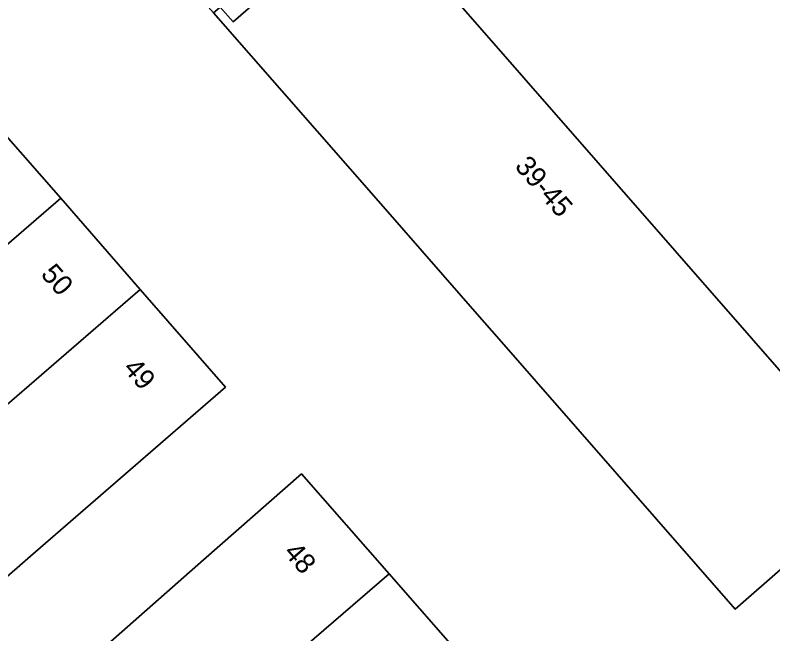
# Model space of a CAD drawing. Extents: x 160663 to 161506, y 382245 to 383291.
# Drawn here: x 160746.63 to 160784.22, y 383063.64 to 383094.33 of the extents above; entities that cross this region are included whole.
import ezdxf

# ---------------------------------------------------------------- set-up
doc = ezdxf.new("R2010")
doc.units = 0
for name, color, linetype in [('IMGEO_Erf', 7, 'Continuous'), ('IMGEO_Pand', 7, 'Continuous'), ('IMGEO_Pand_nummerreeks', 7, 'Continuous'), ('IMGEO_Pand_overbouw', 7, 'Continuous')]:
    doc.layers.add(name, color=color, linetype=linetype)

msp = doc.modelspace()

# ---------------------------------------------------------------- linework, layer by layer
at = {"layer": 'IMGEO_Erf'}
msp.add_lwpolyline([(160789.444, 383076.109), (160791.941, 383073.242), (160782.34, 383064.863), (160770.523, 383078.382), (160769.663, 383079.367), (160765.001, 383084.7), (160756.48, 383094.454), (160756.804, 383094.737), (160757.448, 383093.999), (160764.255, 383099.938), (160786.953, 383073.958)], close=True, dxfattribs=at)
for points in [[(160746.079, 383088.471), (160748.895, 383085.247), (160752.843, 383080.728), (160757.076, 383075.883), (160747.401, 383067.493), (160744.241, 383064.752)], [(160741.394, 383064.67), (160747.56, 383057.614), (160749.218, 383059.06), (160748.08, 383060.364), (160751.236, 383063.118), (160755.975, 383067.307), (160760.845, 383071.574), (160765.185, 383066.611), (160769.134, 383062.095), (160771.856, 383058.982), (160771.879, 383058.88), (160773.339, 383057.204), (160776.347, 383053.751), (160770.736, 383048.852), (160773.152, 383046.089), (160781.278, 383053.198), (160782.484, 383054.246), (160781.181, 383055.738), (160785.226, 383059.27)]]:
    msp.add_lwpolyline(points, dxfattribs=at)
at = {"layer": 'IMGEO_Pand'}
for points in [[(160764.255, 383099.938), (160757.448, 383093.999), (160756.804, 383094.737), (160756.48, 383094.454), (160765.001, 383084.7), (160769.663, 383079.367), (160770.523, 383078.382), (160782.34, 383064.863), (160791.941, 383073.242), (160789.444, 383076.109), (160786.953, 383073.958)], [(160736.016, 383074.127), (160748.895, 383085.247), (160746.079, 383088.471), (160741.125, 383084.148), (160739.68, 383085.812), (160735.027, 383081.714), (160731.764, 383078.977)], [(160736.016, 383074.127), (160739.971, 383069.614), (160752.843, 383080.728), (160748.895, 383085.247)], [(160739.971, 383069.614), (160742.859, 383066.32), (160743.052, 383066.116), (160744.241, 383064.752), (160747.401, 383067.493), (160757.076, 383075.883), (160752.843, 383080.728)], [(160765.185, 383066.611), (160760.845, 383071.574), (160755.975, 383067.307), (160751.236, 383063.118), (160748.08, 383060.364), (160749.218, 383059.06), (160749.42, 383058.859), (160752.347, 383055.527)], [(160756.307, 383051.019), (160769.134, 383062.095), (160765.185, 383066.611), (160752.347, 383055.527)]]:
    msp.add_lwpolyline(points, close=True, dxfattribs=at)
at = {"layer": 'IMGEO_Pand_overbouw'}
msp.add_lwpolyline([(160764.255, 383099.938), (160761.041, 383103.624), (160754.232, 383097.666), (160754.883, 383096.92), (160754.559, 383096.638), (160756.48, 383094.454), (160756.804, 383094.737), (160757.448, 383093.999)], close=True, dxfattribs=at)

# ---------------------------------------------------------------- texts
at = {"layer": 'IMGEO_Pand_nummerreeks'}
for s, rotation, p in [('39-45', 311.1428, (160771.373, 383086.805)), ('50', 311.2546, (160747.864, 383081.449)), ('49', 311.0347, (160751.946, 383076.779)), ('48', 311.0053, (160759.913, 383067.648))]:
    msp.add_text(s, height=1, rotation=rotation, dxfattribs=at).set_placement(p)

doc.saveas('drawing.dxf')
